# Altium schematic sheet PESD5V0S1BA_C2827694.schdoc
size 127 x 101 mm
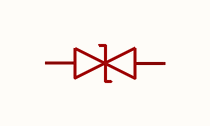
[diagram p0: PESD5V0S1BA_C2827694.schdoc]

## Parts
D?  pesd5v0s1ba  [SOD-323_L1.7-W1.3-LS2.5-BI]  (value not drawn)

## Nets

Not connected (* = marked no-connect by the designer): D? 1 2

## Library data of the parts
D? = pesd5v0s1ba: 极性:双向;反向截止电压(Vrwm):5V;钳位电压:7V；9V;峰值脉冲电流(Ipp):20A;峰值脉冲功率(Ppp):300W@8/20us;击穿电压:7V;; Manufacturer: TECH PUBLIC(台舟); Symbol: PESD5V0S1BA_C2827694; AddInBom: yes; ModelId: 3c4d3117213c44d8be2b8463c3660d20; ModelTransform: 98.425,51.181,0,0,0,0,-0.001,0.006,0; Polarity: 双向; Reverse Stand-Off Voltage (Vrwm): 5V; Clamping Voltage: 7V；9V; Peak Pulse Current (Ipp): 20A; Voltage - Breakdown: 7V; Reverse Leakage Current (Ir): 100nA; Number of Channels: 单路; level of protection: IEC 61000-4-2; Type: ESD; Junction Capacitance: 35pF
